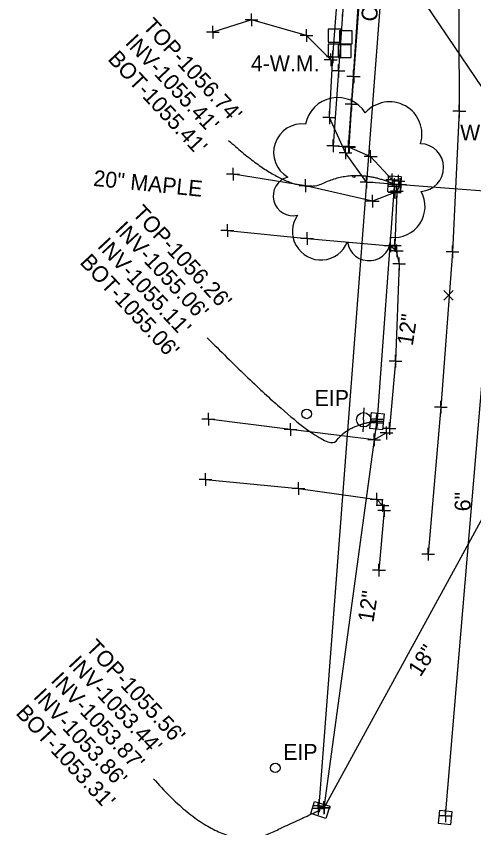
# Model space of a CAD drawing. Extents: x 0 to 1944463, y 0 to 420651.
# Drawn here: x 1942562.5 to 1942706.1, y 417462.6 to 417717.4 of the extents above; entities that cross this region are included whole.
import ezdxf

# ---------------------------------------------------------------- set-up
doc = ezdxf.new("R2010")
doc.units = 0
for name, color, linetype in [('SUR - DRG - Storm Sewer', 7, 'Continuous'), ('SUR - DRG - Storm Sewer - Points - Locators', 7, 'Continuous'), ('SUR - DRG - Storm Sewer Text', 7, 'Continuous'), ('SUR - DTM - Breaklines', 7, 'Continuous'), ('SUR - DTM - Breaklines - Points - Locators', 7, 'Continuous'), ('SUR - PROPERTY - Property Lines', 7, 'Continuous'), ('SUR - PROPERTY - Property Markers', 7, 'Continuous'), ('SUR - TRAN - Features', 7, 'Continuous'), ('SUR - TRAN - Features - Points - Locators', 7, 'Continuous'), ('SUR - TRAN - Features Text', 7, 'Continuous'), ('SUR - TRAN - Roads', 7, 'Continuous'), ('SUR - UTL - Gas', 7, 'Continuous'), ('SUR - UTL - Gas - Points - Locators', 7, 'Continuous'), ('SUR - UTL - Low Wire Crossings', 7, 'Continuous'), ('SUR - UTL - Overhead Wire Crossings', 7, 'Continuous'), ('SUR - UTL - Poles and Miscellaneous', 7, 'Continuous'), ('SUR - UTL - Water', 7, 'Continuous'), ('SUR - UTL - Water - Points - Locators', 7, 'Continuous'), ('SUR - UTL - Water Text', 7, 'Continuous'), ('SUR - VEG - Features', 7, 'Continuous'), ('SUR - VEG - Features - Points - Locators', 7, 'Continuous'), ('SUR - VEG - Features Text', 7, 'Continuous')]:
    doc.layers.add(name, color=color, linetype=linetype)

msp = doc.modelspace()

# ---------------------------------------------------------------- linework, layer by layer
at = {"layer": 'SUR - DRG - Storm Sewer'}
for p, q in [((1942681.23, 417664.72), (1942681.23, 417664.72)), ((1942675.7, 417590.3), (1942675.7, 417590.3)), ((1942657.9, 417468.2), (1942657.9, 417468.2))]:
    msp.add_line(p, q, dxfattribs=at)
for points in [[(1942657.57, 417469.53), (1942684.24, 417818.72)], [(1942683.14, 417662.15), (1942679.14, 417662.29), (1942679.32, 417667.29), (1942683.32, 417667.14), (1942683.14, 417662.15)], [(1942681.11, 417663.98), (1942675.72, 417590.89)], [(1942677.43, 417587.6), (1942673.45, 417588.02), (1942673.96, 417592.99), (1942677.94, 417592.58), (1942677.43, 417587.6)], [(1942675.56, 417589.72), (1942659.02, 417468.89)], [(1942710.62, 417563.16), (1942659.16, 417468.95)], [(1942660.88, 417469.37), (1942659.69, 417465.55), (1942654.92, 417467.04), (1942656.1, 417470.86), (1942660.88, 417469.37)]]:
    msp.add_lwpolyline(points, dxfattribs=at)
at = {"layer": 'SUR - DRG - Storm Sewer - Points - Locators'}
for p, q in [((1942681.23, 417664.62), (1942679.23, 417664.62)), ((1942681.11, 417663.98), (1942681.11, 417665.98)), ((1942681.23, 417664.62), (1942681.23, 417666.62)), ((1942681.23, 417664.62), (1942683.23, 417664.62)), ((1942681.23, 417664.62), (1942681.23, 417662.62)), ((1942681.11, 417663.98), (1942679.11, 417663.98)), ((1942681.11, 417663.98), (1942683.11, 417663.98)), ((1942681.11, 417663.98), (1942681.11, 417661.98)), ((1942675.72, 417590.89), (1942673.72, 417590.89)), ((1942675.56, 417589.72), (1942675.56, 417591.72)), ((1942675.69, 417590.27), (1942675.69, 417592.27)), ((1942675.72, 417590.89), (1942675.72, 417592.89)), ((1942675.72, 417590.89), (1942677.72, 417590.89)), ((1942675.72, 417590.89), (1942675.72, 417588.89)), ((1942675.56, 417589.72), (1942673.56, 417589.72)), ((1942675.69, 417590.27), (1942673.69, 417590.27)), ((1942675.56, 417589.72), (1942677.56, 417589.72)), ((1942675.56, 417589.72), (1942675.56, 417587.72)), ((1942675.69, 417590.27), (1942677.69, 417590.27)), ((1942675.69, 417590.27), (1942675.69, 417588.27)), ((1942657.57, 417469.53), (1942657.57, 417471.53)), ((1942659.02, 417468.89), (1942659.02, 417470.89)), ((1942659.16, 417468.95), (1942659.16, 417470.95)), ((1942657.27, 417468.61), (1942655.27, 417468.61)), ((1942657.57, 417469.53), (1942655.57, 417469.53)), ((1942659.02, 417468.89), (1942657.02, 417468.89)), ((1942659.16, 417468.95), (1942657.16, 417468.95)), ((1942657.27, 417468.61), (1942657.27, 417470.61)), ((1942657.27, 417468.61), (1942659.27, 417468.61)), ((1942657.27, 417468.61), (1942657.27, 417466.61)), ((1942657.57, 417469.53), (1942659.57, 417469.53)), ((1942657.57, 417469.53), (1942657.57, 417467.53)), ((1942659.02, 417468.89), (1942661.02, 417468.89)), ((1942659.02, 417468.89), (1942659.02, 417466.89)), ((1942659.16, 417468.95), (1942661.16, 417468.95)), ((1942659.16, 417468.95), (1942659.16, 417466.95))]:
    msp.add_line(p, q, dxfattribs=at)
at = {"layer": 'SUR - DRG - Storm Sewer Text'}
for points in [[(1942629.15, 417678.41), (1942649.12, 417660.26), (1942669.15, 417669.94), (1942681.23, 417664.72)], [(1942622.42, 417616.48), (1942659.47, 417579.08), (1942666.69, 417589.24), (1942675.7, 417590.3)], [(1942605.54, 417477.99), (1942626.84, 417453.74), (1942657.9, 417468.2), (1942657.9, 417468.2)]]:
    msp.add_open_spline(points, degree=2, dxfattribs=at)
at = {"layer": 'SUR - DTM - Breaklines'}
msp.add_lwpolyline([(1942704.56, 417771.04), (1942701.25, 417740.41), (1942701.55, 417687.57), (1942699.44, 417643.43), (1942695.73, 417594.69), (1942691.79, 417548.54)], dxfattribs=at)
at = {"layer": 'SUR - DTM - Breaklines - Points - Locators'}
for p, q in [((1942701.55, 417687.57), (1942699.55, 417687.57)), ((1942701.55, 417687.57), (1942701.55, 417689.57)), ((1942701.55, 417687.57), (1942703.55, 417687.57)), ((1942701.55, 417687.57), (1942701.55, 417685.57)), ((1942699.44, 417643.43), (1942699.44, 417645.43)), ((1942699.44, 417643.43), (1942697.44, 417643.43)), ((1942699.44, 417643.43), (1942701.44, 417643.43)), ((1942699.44, 417643.43), (1942699.44, 417641.43)), ((1942695.73, 417594.69), (1942695.73, 417596.69)), ((1942695.73, 417594.69), (1942693.73, 417594.69)), ((1942695.73, 417594.69), (1942697.73, 417594.69)), ((1942695.73, 417594.69), (1942695.73, 417592.69)), ((1942691.79, 417548.54), (1942691.79, 417550.54)), ((1942691.79, 417548.54), (1942689.79, 417548.54)), ((1942691.79, 417548.54), (1942693.79, 417548.54)), ((1942691.79, 417548.54), (1942691.79, 417546.54))]:
    msp.add_line(p, q, dxfattribs=at)
at = {"layer": 'SUR - PROPERTY - Property Lines'}
for p, q in [((1942668.4, 417698.45), (1942668.4, 417700.45)), ((1942668.4, 417698.45), (1942666.4, 417698.45)), ((1942668.4, 417698.45), (1942670.4, 417698.45)), ((1942668.4, 417698.45), (1942668.4, 417696.45)), ((1942666.95, 417676.33), (1942666.95, 417678.33)), ((1942666.95, 417676.33), (1942664.95, 417676.33)), ((1942666.95, 417676.33), (1942668.95, 417676.33)), ((1942666.95, 417676.33), (1942666.95, 417674.33)), ((1942673.72, 417673.34), (1942673.72, 417675.34)), ((1942673.72, 417673.34), (1942671.72, 417673.34)), ((1942673.72, 417673.34), (1942675.72, 417673.34)), ((1942673.72, 417673.34), (1942673.72, 417671.34)), ((1942680.49, 417666.06), (1942680.49, 417668.06)), ((1942682.43, 417665.63), (1942682.43, 417667.63)), ((1942680.49, 417666.06), (1942678.49, 417666.06)), ((1942682.43, 417665.63), (1942680.43, 417665.63)), ((1942680.49, 417666.06), (1942682.49, 417666.06)), ((1942680.49, 417666.06), (1942680.49, 417664.06)), ((1942683.01, 417664.58), (1942681.01, 417664.58)), ((1942681.97, 417662.53), (1942681.97, 417664.53)), ((1942682.43, 417665.63), (1942684.43, 417665.63)), ((1942682.43, 417665.63), (1942682.43, 417663.63)), ((1942683.01, 417664.58), (1942683.01, 417666.58)), ((1942683.01, 417664.58), (1942685.01, 417664.58)), ((1942683.01, 417664.58), (1942683.01, 417662.58)), ((1942681.97, 417662.53), (1942679.97, 417662.53)), ((1942681.97, 417662.53), (1942683.97, 417662.53)), ((1942681.97, 417662.53), (1942681.97, 417660.53)), ((1942681.31, 417645.45), (1942681.31, 417647.45)), ((1942681.31, 417645.45), (1942679.31, 417645.45)), ((1942681.31, 417645.45), (1942683.31, 417645.45)), ((1942681.31, 417645.45), (1942681.31, 417643.45)), ((1942682.68, 417639.66), (1942682.68, 417641.66)), ((1942682.68, 417639.66), (1942680.68, 417639.66)), ((1942682.68, 417639.66), (1942684.68, 417639.66)), ((1942682.68, 417639.66), (1942682.68, 417637.66)), ((1942681.54, 417609.13), (1942681.54, 417611.13)), ((1942681.54, 417609.13), (1942679.54, 417609.13)), ((1942681.54, 417609.13), (1942683.54, 417609.13)), ((1942681.54, 417609.13), (1942681.54, 417607.13)), ((1942679.62, 417587.93), (1942677.62, 417587.93)), ((1942679.62, 417587.93), (1942679.62, 417589.93)), ((1942679.62, 417587.93), (1942681.62, 417587.93)), ((1942679.62, 417587.93), (1942679.62, 417585.93)), ((1942678, 417562.24), (1942678, 417564.24)), ((1942678, 417562.24), (1942676, 417562.24)), ((1942678, 417562.24), (1942680, 417562.24)), ((1942678, 417562.24), (1942678, 417560.24)), ((1942676.34, 417543.46), (1942676.34, 417545.46)), ((1942676.34, 417543.46), (1942674.34, 417543.46)), ((1942676.34, 417543.46), (1942678.34, 417543.46)), ((1942676.34, 417543.46), (1942676.34, 417541.46))]:
    msp.add_line(p, q, dxfattribs=at)
at = {"layer": 'SUR - PROPERTY - Property Markers'}
for centre in [(1942653.65, 417592.55), (1942643.79, 417481.4)]:
    msp.add_circle(centre, 1.5, dxfattribs=at)
at = {"layer": 'SUR - TRAN - Features'}
for points in [[(1942675.8, 417775.09), (1942672.74, 417744.67), (1942671.7, 417733.84), (1942671.11, 417733.93), (1942669.88, 417719.63), (1942667.76, 417689.81), (1942666.83, 417676.52)], [(1942665.05, 417721.03), (1942663.62, 417700.23), (1942661.93, 417676.72), (1942666.75, 417676.46), (1942668.3, 417698.49), (1942669.78, 417720.39)], [(1942681.26, 417662.05), (1942674.35, 417659.37), (1942653.27, 417664.22), (1942630.53, 417667.87)], [(1942628.76, 417650.14), (1942653.78, 417647.65), (1942679.96, 417645.3), (1942681.92, 417643.75)], [(1942678.68, 417586.56), (1942674.85, 417584.38), (1942648.58, 417587.65), (1942622.79, 417590.9)], [(1942621.89, 417571.93), (1942651.07, 417569.11), (1942675.62, 417565.72), (1942677.41, 417563.75)]]:
    msp.add_lwpolyline(points, dxfattribs=at)
at = {"layer": 'SUR - TRAN - Features - Points - Locators'}
for p, q in [((1942663.62, 417700.23), (1942661.62, 417700.23)), ((1942663.62, 417700.23), (1942663.62, 417702.23)), ((1942663.62, 417700.23), (1942665.62, 417700.23)), ((1942663.62, 417700.23), (1942663.62, 417698.23)), ((1942668.3, 417698.49), (1942668.3, 417700.49)), ((1942668.3, 417698.49), (1942666.3, 417698.49)), ((1942668.3, 417698.49), (1942670.3, 417698.49)), ((1942668.3, 417698.49), (1942668.3, 417696.49)), ((1942667.76, 417689.81), (1942667.76, 417691.81)), ((1942667.76, 417689.81), (1942665.76, 417689.81)), ((1942667.76, 417689.81), (1942669.76, 417689.81)), ((1942667.76, 417689.81), (1942667.76, 417687.81)), ((1942661.93, 417676.72), (1942661.93, 417678.72)), ((1942666.75, 417676.46), (1942666.75, 417678.46)), ((1942666.83, 417676.52), (1942666.83, 417678.52)), ((1942661.93, 417676.72), (1942659.93, 417676.72)), ((1942661.93, 417676.72), (1942663.93, 417676.72)), ((1942661.93, 417676.72), (1942661.93, 417674.72)), ((1942666.75, 417676.46), (1942664.75, 417676.46)), ((1942666.83, 417676.52), (1942664.83, 417676.52)), ((1942666.75, 417676.46), (1942668.75, 417676.46)), ((1942666.75, 417676.46), (1942666.75, 417674.46)), ((1942666.83, 417676.52), (1942668.83, 417676.52)), ((1942666.83, 417676.52), (1942666.83, 417674.52)), ((1942630.53, 417667.87), (1942630.53, 417669.87)), ((1942630.53, 417667.87), (1942628.53, 417667.87)), ((1942630.53, 417667.87), (1942632.53, 417667.87)), ((1942630.53, 417667.87), (1942630.53, 417665.87)), ((1942653.27, 417664.22), (1942653.27, 417666.22)), ((1942653.27, 417664.22), (1942651.27, 417664.22)), ((1942653.27, 417664.22), (1942655.27, 417664.22)), ((1942653.27, 417664.22), (1942653.27, 417662.22)), ((1942681.26, 417662.05), (1942679.26, 417662.05)), ((1942681.26, 417662.05), (1942681.26, 417664.05)), ((1942681.26, 417662.05), (1942683.26, 417662.05)), ((1942681.26, 417662.05), (1942681.26, 417660.05)), ((1942674.35, 417659.37), (1942672.35, 417659.37)), ((1942674.35, 417659.37), (1942674.35, 417661.37)), ((1942674.35, 417659.37), (1942676.35, 417659.37)), ((1942674.35, 417659.37), (1942674.35, 417657.37)), ((1942628.76, 417650.14), (1942628.76, 417652.14)), ((1942628.76, 417650.14), (1942626.76, 417650.14)), ((1942628.76, 417650.14), (1942630.76, 417650.14)), ((1942628.76, 417650.14), (1942628.76, 417648.14)), ((1942653.78, 417647.65), (1942653.78, 417649.65)), ((1942653.78, 417647.65), (1942651.78, 417647.65)), ((1942653.78, 417647.65), (1942655.78, 417647.65)), ((1942653.78, 417647.65), (1942653.78, 417645.65)), ((1942679.96, 417645.3), (1942679.96, 417647.3)), ((1942679.96, 417645.3), (1942677.96, 417645.3)), ((1942679.96, 417645.3), (1942681.96, 417645.3)), ((1942679.96, 417645.3), (1942679.96, 417643.3)), ((1942681.92, 417643.75), (1942681.92, 417645.75)), ((1942681.92, 417643.75), (1942679.92, 417643.75)), ((1942681.92, 417643.75), (1942683.92, 417643.75)), ((1942681.92, 417643.75), (1942681.92, 417641.75)), ((1942622.79, 417590.9), (1942620.79, 417590.9)), ((1942622.79, 417590.9), (1942622.79, 417592.9)), ((1942622.79, 417590.9), (1942624.79, 417590.9)), ((1942622.79, 417590.9), (1942622.79, 417588.9)), ((1942648.58, 417587.65), (1942648.58, 417589.65)), ((1942678.68, 417586.56), (1942678.68, 417588.56)), ((1942648.58, 417587.65), (1942646.58, 417587.65)), ((1942648.58, 417587.65), (1942650.58, 417587.65)), ((1942648.58, 417587.65), (1942648.58, 417585.65)), ((1942674.85, 417584.38), (1942674.85, 417586.38)), ((1942678.68, 417586.56), (1942676.68, 417586.56)), ((1942678.68, 417586.56), (1942680.68, 417586.56)), ((1942678.68, 417586.56), (1942678.68, 417584.56)), ((1942674.85, 417584.38), (1942672.85, 417584.38)), ((1942674.85, 417584.38), (1942676.85, 417584.38)), ((1942674.85, 417584.38), (1942674.85, 417582.38)), ((1942621.89, 417571.93), (1942621.89, 417573.93)), ((1942621.89, 417571.93), (1942619.89, 417571.93)), ((1942621.89, 417571.93), (1942623.89, 417571.93)), ((1942621.89, 417571.93), (1942621.89, 417569.93)), ((1942651.07, 417569.11), (1942651.07, 417571.11)), ((1942651.07, 417569.11), (1942649.07, 417569.11)), ((1942651.07, 417569.11), (1942653.07, 417569.11)), ((1942651.07, 417569.11), (1942651.07, 417567.11)), ((1942675.62, 417565.72), (1942675.62, 417567.72)), ((1942675.62, 417565.72), (1942673.62, 417565.72)), ((1942675.62, 417565.72), (1942677.62, 417565.72)), ((1942675.62, 417565.72), (1942675.62, 417563.72)), ((1942677.41, 417563.75), (1942677.41, 417565.75)), ((1942677.41, 417563.75), (1942675.41, 417563.75)), ((1942677.41, 417563.75), (1942679.41, 417563.75)), ((1942677.41, 417563.75), (1942677.41, 417561.75))]:
    msp.add_line(p, q, dxfattribs=at)
at = {"layer": 'SUR - TRAN - Roads'}
for points in [[(1942666.95, 417676.33), (1942673.72, 417673.34), (1942680.49, 417666.06), (1942682.43, 417665.63), (1942683.01, 417664.58), (1942681.97, 417662.53), (1942681.31, 417645.45), (1942682.68, 417639.66), (1942681.54, 417609.13), (1942679.62, 417587.93)], [(1942678, 417562.24), (1942676.34, 417543.46)]]:
    msp.add_lwpolyline(points, dxfattribs=at)
at = {"layer": 'SUR - UTL - Gas'}
for points in [[(1942761.94, 417666.33), (1942760.67, 417660.51), (1942749.53, 417660.1), (1942728.34, 417662.86), (1942716.17, 417661.92), (1942672.46, 417665.32), (1942665.83, 417674.56), (1942660.77, 417685.58), (1942661.84, 417704.71), (1942664.98, 417745.5), (1942666.88, 417768.86)], [(1942661.18, 417703.75), (1942653.57, 417711.37), (1942636.35, 417716.3), (1942624.17, 417712.43)]]:
    msp.add_lwpolyline(points, dxfattribs=at)
at = {"layer": 'SUR - UTL - Gas - Points - Locators'}
for p, q in [((1942636.35, 417716.3), (1942636.35, 417718.3)), ((1942636.35, 417716.3), (1942634.35, 417716.3)), ((1942636.35, 417716.3), (1942638.35, 417716.3)), ((1942636.35, 417716.3), (1942636.35, 417714.3)), ((1942624.17, 417712.43), (1942624.17, 417714.43)), ((1942653.57, 417711.37), (1942653.57, 417713.37)), ((1942624.17, 417712.43), (1942622.17, 417712.43)), ((1942624.17, 417712.43), (1942626.17, 417712.43)), ((1942624.17, 417712.43), (1942624.17, 417710.43)), ((1942653.57, 417711.37), (1942651.57, 417711.37)), ((1942653.57, 417711.37), (1942655.57, 417711.37)), ((1942653.57, 417711.37), (1942653.57, 417709.37)), ((1942661.18, 417703.75), (1942661.18, 417705.75)), ((1942661.84, 417704.71), (1942661.84, 417706.71)), ((1942661.18, 417703.75), (1942659.18, 417703.75)), ((1942661.84, 417704.71), (1942659.84, 417704.71)), ((1942661.18, 417703.75), (1942663.18, 417703.75)), ((1942661.18, 417703.75), (1942661.18, 417701.75)), ((1942661.84, 417704.71), (1942663.84, 417704.71)), ((1942661.84, 417704.71), (1942661.84, 417702.71)), ((1942660.77, 417685.58), (1942660.77, 417687.58)), ((1942660.77, 417685.58), (1942658.77, 417685.58)), ((1942660.77, 417685.58), (1942662.77, 417685.58)), ((1942660.77, 417685.58), (1942660.77, 417683.58)), ((1942665.83, 417674.56), (1942663.83, 417674.56)), ((1942665.83, 417674.56), (1942665.83, 417676.56)), ((1942665.83, 417674.56), (1942667.83, 417674.56)), ((1942665.83, 417674.56), (1942665.83, 417672.56)), ((1942672.46, 417665.32), (1942672.46, 417667.32)), ((1942672.46, 417665.32), (1942672.46, 417667.32)), ((1942672.46, 417665.32), (1942670.46, 417665.32)), ((1942672.46, 417665.32), (1942670.46, 417665.32)), ((1942672.46, 417665.32), (1942674.46, 417665.32)), ((1942672.46, 417665.32), (1942672.46, 417663.32)), ((1942672.46, 417665.32), (1942674.46, 417665.32)), ((1942672.46, 417665.32), (1942672.46, 417663.32))]:
    msp.add_line(p, q, dxfattribs=at)
at = {"layer": 'SUR - UTL - Low Wire Crossings'}
for p, q in [((1942696.64, 417631.31), (1942699.64, 417628.31)), ((1942699.64, 417631.31), (1942696.64, 417628.31)), ((1942698.14, 417629.81), (1942698.14, 417629.81))]:
    msp.add_line(p, q, dxfattribs=at)
at = {"layer": 'SUR - UTL - Overhead Wire Crossings'}
msp.add_lwpolyline([(1942628.18, 417814.1), (1942724.56, 417671.61)], dxfattribs=at)
at = {"layer": 'SUR - UTL - Poles and Miscellaneous'}
for q in [(1942671.73, 417594.46), (1942671.32, 417586.97)]:
    msp.add_line((1942671.52, 417590.71), q, dxfattribs=at)
msp.add_circle((1942671.52, 417590.71), 2.25, dxfattribs=at)
at = {"layer": 'SUR - UTL - Water'}
for p, q in [((1942662.38, 417711.33), (1942662.38, 417711.33)), ((1942665.97, 417710.79), (1942665.97, 417710.79)), ((1942662.38, 417706.66), (1942662.38, 417706.66)), ((1942665.57, 417706.45), (1942665.57, 417706.45)), ((1942697.13, 417465.79), (1942697.13, 417465.79))]:
    msp.add_line(p, q, dxfattribs=at)
for points in [[(1942660.38, 417713.33), (1942660.38, 417709.33), (1942664.38, 417709.33), (1942664.38, 417713.33), (1942660.38, 417713.33)], [(1942663.97, 417712.79), (1942663.97, 417708.79), (1942667.97, 417708.79), (1942667.97, 417712.79), (1942663.97, 417712.79)], [(1942660.38, 417708.66), (1942660.38, 417704.66), (1942664.38, 417704.66), (1942664.38, 417708.66), (1942660.38, 417708.66)], [(1942663.57, 417708.45), (1942663.57, 417704.45), (1942667.57, 417704.45), (1942667.57, 417708.45), (1942663.57, 417708.45)], [(1942697.2, 417466.36), (1942715.7, 417685.81)], [(1942698.91, 417463.59), (1942699.34, 417467.57), (1942695.36, 417468), (1942694.93, 417464.02), (1942698.91, 417463.59)]]:
    msp.add_lwpolyline(points, dxfattribs=at)
at = {"layer": 'SUR - UTL - Water - Points - Locators'}
for q in [(1942697.2, 417468.36), (1942695.2, 417466.36), (1942699.2, 417466.36), (1942697.2, 417464.36)]:
    msp.add_line((1942697.2, 417466.36), q, dxfattribs=at)
at = {"layer": 'SUR - VEG - Features'}
msp.add_circle((1942668.49, 417667.09), 0.313, dxfattribs=at)
for centre, radius, start, end in [((1942663.37, 417681.67), 10.22, 31.9683, 169.4925), ((1942679.67, 417680.38), 10.16, 342.8641, 138.7026), ((1942652.24, 417674.64), 8.97, 82.9155, 239.7044), ((1942689.13, 417669.91), 7.49, 273.117, 88.1173), ((1942649.31, 417660.94), 6.16, 105.0317, 283.7773), ((1942681.16, 417657.63), 9.65, 262.9581, 29.8037), ((1942658.11, 417649.83), 8.95, 145.0523, 338.472), ((1942673.19, 417647.46), 6.81, 187.671, 4.9902)]:
    msp.add_arc(centre, radius, start, end, dxfattribs=at)
at = {"layer": 'SUR - VEG - Features - Points - Locators'}
msp.add_line((1942664.79, 417718.02), (1942664.79, 417716.02), dxfattribs=at)

# ---------------------------------------------------------------- texts
at = {"layer": 'SUR - DRG - Storm Sewer Text'}
for s, rotation, p in [("TOP-1056.74'", 313, (1942601.94, 417714.01)), ("INV-1055.41'", 313, (1942596.45, 417708.9)), ("BOT-1055.41'", 313, (1942590.97, 417703.78)), ("TOP-1056.26'", 313, (1942598.68, 417655.27)), ("INV-1055.06'", 313, (1942593.19, 417650.16)), ("INV-1055.11'", 313, (1942587.71, 417645.04)), ("BOT-1055.06'", 313, (1942582.22, 417639.93)), ('12"', 81.1237, (1942686.91, 417613.77)), ('12"', 81.1237, (1942674.57, 417526.87)), ("TOP-1055.56'", 313, (1942584.07, 417518.86)), ('18"', 57.0642, (1942689.31, 417509.71)), ("INV-1053.44'", 313, (1942578.59, 417513.75)), ("INV-1053.87'", 313, (1942573.1, 417508.63)), ("INV-1053.86'", 313, (1942567.62, 417503.52)), ("BOT-1053.31'", 313, (1942562.13, 417498.4))]:
    msp.add_text(s, height=5, rotation=rotation, dxfattribs=at).set_placement(p)
at = {"layer": 'SUR - PROPERTY - Property Markers'}
for p in [(1942656.15, 417595.05), (1942646.29, 417483.9)]:
    msp.add_text('EIP', height=5, dxfattribs=at).set_placement(p)
at = {"layer": 'SUR - TRAN - Features Text'}
msp.add_text('CONC.', height=5, rotation=86.1023, dxfattribs=at).set_placement((1942675.72, 417715.64))
at = {"layer": 'SUR - UTL - Water Text'}
for s, p in [('4-W.M.', (1942636.13, 417700.12)), ('W.V.', (1942701.8, 417678.42))]:
    msp.add_text(s, height=5, dxfattribs=at).set_placement(p)
msp.add_text('6"', height=5, rotation=90, dxfattribs=at).set_placement((1942705.09, 417561.97))
at = {"layer": 'SUR - VEG - Features Text'}
msp.add_text('20" MAPLE', height=5, rotation=354.2225, dxfattribs=at).set_placement((1942586.53, 417664.17))

doc.saveas('drawing.dxf')
